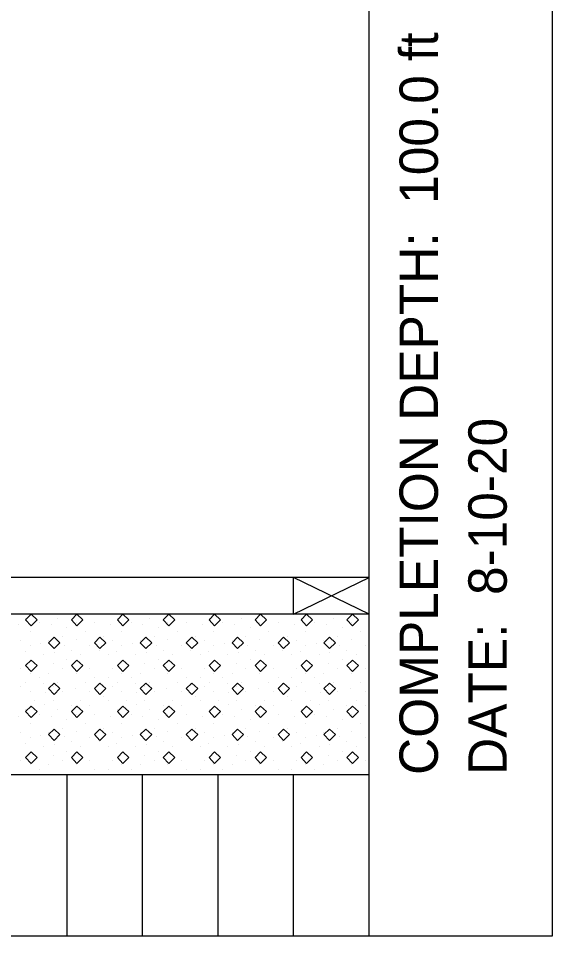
# Model space of a CAD drawing. Extents: x 1313964 to 1316843, y 2087046 to 2096619.
# Drawn here: x 1314029.73 to 1314036.8, y 2089873.43 to 2089885.58 of the extents above; entities that cross this region are included whole.
import ezdxf

# ---------------------------------------------------------------- set-up
doc = ezdxf.new("R2010")
doc.units = 0
doc.layers.add('B-Sub-Contour', color=7, linetype='Continuous')
doc.layers.add('Default', color=7, linetype='Continuous')

# ---------------------------------------------------------------- blocks, each defined once
blk = doc.blocks.new('POINT_DISPLAY')
at = {"layer": 'Default'}
blk.add_line((0, 0), (0, 0), dxfattribs=at)

msp = doc.modelspace()

# ---------------------------------------------------------------- linework, layer by layer
at = {"layer": 'B-Sub-Contour'}
for points in [[(1314036.804, 2089873.434), (1314036.804, 2089916.306), (1313975.385, 2089916.306), (1313975.385, 2089873.434), (1314036.804, 2089873.434)], [(1314034.372, 2089873.434), (1314034.372, 2089916.306)], [(1314034.372, 2089878.178), (1313989.372, 2089878.178)], [(1314033.372, 2089877.691), (1314034.372, 2089878.178)], [(1314034.372, 2089877.691), (1314033.372, 2089878.178)], [(1314033.372, 2089877.691), (1314033.372, 2089878.178)], [(1314034.372, 2089877.691), (1314034.372, 2089878.178)], [(1314034.372, 2089877.691), (1313982.683, 2089877.691)], [(1314034.372, 2089875.563), (1313982.683, 2089875.563)], [(1314030.372, 2089873.434), (1314030.372, 2089875.563)], [(1314030.372, 2089873.434), (1314030.372, 2089875.563)], [(1314031.372, 2089873.434), (1314031.372, 2089875.563)], [(1314032.372, 2089873.434), (1314032.372, 2089875.563)], [(1314032.372, 2089873.434), (1314032.372, 2089875.563)], [(1314033.372, 2089873.434), (1314033.372, 2089875.563)], [(1314034.372, 2089875.319), (1314034.372, 2089875.563)], [(1314034.372, 2089875.319), (1314034.372, 2089875.563)], [(1314034.372, 2089873.434), (1314034.372, 2089873.678)], [(1314034.372, 2089873.434), (1314034.372, 2089873.678)]]:
    msp.add_lwpolyline(points, dxfattribs=at)
for points in [[(1314029.894, 2089877.691), (1314029.821, 2089877.618), (1314029.894, 2089877.539), (1314029.973, 2089877.618)], [(1314030.502, 2089877.691), (1314030.429, 2089877.618), (1314030.502, 2089877.539), (1314030.581, 2089877.618)], [(1314031.11, 2089877.691), (1314031.037, 2089877.618), (1314031.11, 2089877.539), (1314031.189, 2089877.618)], [(1314031.718, 2089877.691), (1314031.645, 2089877.618), (1314031.718, 2089877.539), (1314031.797, 2089877.618)], [(1314032.326, 2089877.691), (1314032.253, 2089877.618), (1314032.326, 2089877.539), (1314032.405, 2089877.618)], [(1314032.934, 2089877.691), (1314032.861, 2089877.618), (1314032.934, 2089877.539), (1314033.014, 2089877.618)], [(1314033.543, 2089877.691), (1314033.47, 2089877.618), (1314033.543, 2089877.539), (1314033.622, 2089877.618)], [(1314034.151, 2089877.691), (1314034.078, 2089877.618), (1314034.151, 2089877.539), (1314034.23, 2089877.618)], [(1314030.198, 2089877.387), (1314030.125, 2089877.314), (1314030.198, 2089877.235), (1314030.277, 2089877.314)], [(1314030.806, 2089877.387), (1314030.733, 2089877.314), (1314030.806, 2089877.235), (1314030.885, 2089877.314)], [(1314031.414, 2089877.387), (1314031.341, 2089877.314), (1314031.414, 2089877.235), (1314031.493, 2089877.314)], [(1314032.022, 2089877.387), (1314031.949, 2089877.314), (1314032.022, 2089877.235), (1314032.101, 2089877.314)], [(1314032.63, 2089877.387), (1314032.557, 2089877.314), (1314032.63, 2089877.235), (1314032.709, 2089877.314)], [(1314033.239, 2089877.387), (1314033.166, 2089877.314), (1314033.239, 2089877.235), (1314033.318, 2089877.314)], [(1314033.847, 2089877.387), (1314033.774, 2089877.314), (1314033.847, 2089877.235), (1314033.926, 2089877.314)], [(1314029.894, 2089877.083), (1314029.821, 2089877.01), (1314029.894, 2089876.931), (1314029.973, 2089877.01)], [(1314030.502, 2089877.083), (1314030.429, 2089877.01), (1314030.502, 2089876.931), (1314030.581, 2089877.01)], [(1314031.11, 2089877.083), (1314031.037, 2089877.01), (1314031.11, 2089876.931), (1314031.189, 2089877.01)], [(1314031.718, 2089877.083), (1314031.645, 2089877.01), (1314031.718, 2089876.931), (1314031.797, 2089877.01)], [(1314032.326, 2089877.083), (1314032.253, 2089877.01), (1314032.326, 2089876.931), (1314032.405, 2089877.01)], [(1314032.934, 2089877.083), (1314032.861, 2089877.01), (1314032.934, 2089876.931), (1314033.014, 2089877.01)], [(1314033.543, 2089877.083), (1314033.47, 2089877.01), (1314033.543, 2089876.931), (1314033.622, 2089877.01)], [(1314034.151, 2089877.083), (1314034.078, 2089877.01), (1314034.151, 2089876.931), (1314034.23, 2089877.01)], [(1314030.198, 2089876.779), (1314030.125, 2089876.706), (1314030.198, 2089876.627), (1314030.277, 2089876.706)], [(1314030.806, 2089876.779), (1314030.733, 2089876.706), (1314030.806, 2089876.627), (1314030.885, 2089876.706)], [(1314031.414, 2089876.779), (1314031.341, 2089876.706), (1314031.414, 2089876.627), (1314031.493, 2089876.706)], [(1314032.022, 2089876.779), (1314031.949, 2089876.706), (1314032.022, 2089876.627), (1314032.101, 2089876.706)], [(1314032.63, 2089876.779), (1314032.557, 2089876.706), (1314032.63, 2089876.627), (1314032.709, 2089876.706)], [(1314033.239, 2089876.779), (1314033.166, 2089876.706), (1314033.239, 2089876.627), (1314033.318, 2089876.706)], [(1314033.847, 2089876.779), (1314033.774, 2089876.706), (1314033.847, 2089876.627), (1314033.926, 2089876.706)], [(1314029.894, 2089876.475), (1314029.821, 2089876.402), (1314029.894, 2089876.323), (1314029.973, 2089876.402)], [(1314030.502, 2089876.475), (1314030.429, 2089876.402), (1314030.502, 2089876.323), (1314030.581, 2089876.402)], [(1314031.11, 2089876.475), (1314031.037, 2089876.402), (1314031.11, 2089876.323), (1314031.189, 2089876.402)], [(1314031.718, 2089876.475), (1314031.645, 2089876.402), (1314031.718, 2089876.323), (1314031.797, 2089876.402)], [(1314032.326, 2089876.475), (1314032.253, 2089876.402), (1314032.326, 2089876.323), (1314032.405, 2089876.402)], [(1314032.934, 2089876.475), (1314032.861, 2089876.402), (1314032.934, 2089876.323), (1314033.014, 2089876.402)], [(1314033.543, 2089876.475), (1314033.47, 2089876.402), (1314033.543, 2089876.323), (1314033.622, 2089876.402)], [(1314034.151, 2089876.475), (1314034.078, 2089876.402), (1314034.151, 2089876.323), (1314034.23, 2089876.402)], [(1314030.198, 2089876.171), (1314030.125, 2089876.098), (1314030.198, 2089876.019), (1314030.277, 2089876.098)], [(1314030.806, 2089876.171), (1314030.733, 2089876.098), (1314030.806, 2089876.019), (1314030.885, 2089876.098)], [(1314031.414, 2089876.171), (1314031.341, 2089876.098), (1314031.414, 2089876.019), (1314031.493, 2089876.098)], [(1314032.022, 2089876.171), (1314031.949, 2089876.098), (1314032.022, 2089876.019), (1314032.101, 2089876.098)], [(1314032.63, 2089876.171), (1314032.557, 2089876.098), (1314032.63, 2089876.019), (1314032.709, 2089876.098)], [(1314033.239, 2089876.171), (1314033.166, 2089876.098), (1314033.239, 2089876.019), (1314033.318, 2089876.098)], [(1314033.847, 2089876.171), (1314033.774, 2089876.098), (1314033.847, 2089876.019), (1314033.926, 2089876.098)], [(1314029.894, 2089875.867), (1314029.821, 2089875.794), (1314029.894, 2089875.715), (1314029.973, 2089875.794)], [(1314030.502, 2089875.867), (1314030.429, 2089875.794), (1314030.502, 2089875.715), (1314030.581, 2089875.794)], [(1314031.11, 2089875.867), (1314031.037, 2089875.794), (1314031.11, 2089875.715), (1314031.189, 2089875.794)], [(1314031.718, 2089875.867), (1314031.645, 2089875.794), (1314031.718, 2089875.715), (1314031.797, 2089875.794)], [(1314032.326, 2089875.867), (1314032.253, 2089875.794), (1314032.326, 2089875.715), (1314032.405, 2089875.794)], [(1314032.934, 2089875.867), (1314032.861, 2089875.794), (1314032.934, 2089875.715), (1314033.014, 2089875.794)], [(1314033.543, 2089875.867), (1314033.47, 2089875.794), (1314033.543, 2089875.715), (1314033.622, 2089875.794)], [(1314034.151, 2089875.867), (1314034.078, 2089875.794), (1314034.151, 2089875.715), (1314034.23, 2089875.794)]]:
    msp.add_lwpolyline(points, close=True, dxfattribs=at)

# ---------------------------------------------------------------- block references
at = {"layer": 'B-Sub-Contour', "xscale": 0.019951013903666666, "yscale": 0.019951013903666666, "rotation": 90}
for p in [(1314029.821, 2089877.641), (1314030.247, 2089877.641), (1314031.037, 2089877.641), (1314031.463, 2089877.641), (1314032.253, 2089877.641), (1314032.679, 2089877.641), (1314033.47, 2089877.641), (1314033.895, 2089877.641), (1314029.73, 2089877.555), (1314030.003, 2089877.58), (1314030.158, 2089877.552), (1314030.368, 2089877.519), (1314030.49, 2089877.58), (1314030.733, 2089877.58), (1314030.946, 2089877.555), (1314031.22, 2089877.58), (1314031.374, 2089877.552), (1314031.584, 2089877.519), (1314031.706, 2089877.58), (1314031.949, 2089877.58), (1314032.162, 2089877.555), (1314032.436, 2089877.58), (1314032.591, 2089877.552), (1314032.801, 2089877.519), (1314032.922, 2089877.58), (1314033.166, 2089877.58), (1314033.378, 2089877.555), (1314033.652, 2089877.58), (1314033.807, 2089877.552), (1314034.017, 2089877.519), (1314034.139, 2089877.58), (1314029.882, 2089877.458), (1314030.307, 2089877.398), (1314030.611, 2089877.458), (1314030.855, 2089877.398), (1314031.098, 2089877.458), (1314031.524, 2089877.398), (1314031.828, 2089877.458), (1314032.071, 2089877.398), (1314032.314, 2089877.458), (1314032.74, 2089877.398), (1314033.044, 2089877.458), (1314033.287, 2089877.398), (1314033.53, 2089877.458), (1314033.956, 2089877.398), (1314034.26, 2089877.458), (1314029.76, 2089877.337), (1314029.882, 2089877.276), (1314030.02, 2089877.307), (1314030.125, 2089877.337), (1314030.332, 2089877.282), (1314030.49, 2089877.359), (1314030.672, 2089877.276), (1314030.976, 2089877.337), (1314031.098, 2089877.276), (1314031.236, 2089877.307), (1314031.341, 2089877.337), (1314031.549, 2089877.282), (1314031.706, 2089877.359), (1314031.889, 2089877.276), (1314032.193, 2089877.337), (1314032.314, 2089877.276), (1314032.452, 2089877.307), (1314032.557, 2089877.337), (1314032.765, 2089877.282), (1314032.922, 2089877.359), (1314033.105, 2089877.276), (1314033.409, 2089877.337), (1314033.53, 2089877.276), (1314033.669, 2089877.307), (1314033.774, 2089877.337), (1314033.981, 2089877.282), (1314034.139, 2089877.359), (1314034.321, 2089877.276), (1314029.815, 2089877.196), (1314030.064, 2089877.154), (1314030.205, 2089877.188), (1314030.429, 2089877.215), (1314030.551, 2089877.154), (1314030.794, 2089877.215), (1314030.916, 2089877.154), (1314031.032, 2089877.196), (1314031.28, 2089877.154), (1314031.421, 2089877.188), (1314031.645, 2089877.215), (1314031.767, 2089877.154), (1314032.01, 2089877.215), (1314032.132, 2089877.154), (1314032.248, 2089877.196), (1314032.497, 2089877.154), (1314032.638, 2089877.188), (1314032.861, 2089877.215), (1314032.983, 2089877.154), (1314033.226, 2089877.215), (1314033.348, 2089877.154), (1314033.464, 2089877.196), (1314033.713, 2089877.154), (1314033.854, 2089877.188), (1314034.078, 2089877.215), (1314034.199, 2089877.154), (1314029.943, 2089877.033), (1314030.186, 2089877.033), (1314030.368, 2089877.094), (1314031.159, 2089877.033), (1314031.402, 2089877.033), (1314031.584, 2089877.094), (1314032.375, 2089877.033), (1314032.618, 2089877.033), (1314032.801, 2089877.094), (1314033.591, 2089877.033), (1314033.834, 2089877.033), (1314034.017, 2089877.094), (1314029.76, 2089876.972), (1314029.882, 2089876.911), (1314030.125, 2089876.911), (1314030.307, 2089876.972), (1314030.49, 2089876.911), (1314030.672, 2089876.972), (1314030.976, 2089876.972), (1314031.098, 2089876.911), (1314031.341, 2089876.911), (1314031.524, 2089876.972), (1314031.706, 2089876.911), (1314031.889, 2089876.972), (1314032.193, 2089876.972), (1314032.314, 2089876.911), (1314032.557, 2089876.911), (1314032.74, 2089876.972), (1314032.922, 2089876.911), (1314033.105, 2089876.972), (1314033.409, 2089876.972), (1314033.53, 2089876.911), (1314033.774, 2089876.911), (1314033.956, 2089876.972), (1314034.139, 2089876.911), (1314034.321, 2089876.972), (1314029.821, 2089876.79), (1314030.003, 2089876.85), (1314030.247, 2089876.79), (1314030.611, 2089876.79), (1314030.733, 2089876.85), (1314030.794, 2089876.776), (1314030.916, 2089876.85), (1314031.037, 2089876.79), (1314031.22, 2089876.85), (1314031.463, 2089876.79), (1314031.828, 2089876.79), (1314031.949, 2089876.85), (1314032.01, 2089876.776), (1314032.132, 2089876.85), (1314032.253, 2089876.79), (1314032.436, 2089876.85), (1314032.679, 2089876.79), (1314033.044, 2089876.79), (1314033.166, 2089876.85), (1314033.226, 2089876.776), (1314033.348, 2089876.85), (1314033.47, 2089876.79), (1314033.652, 2089876.85), (1314033.895, 2089876.79), (1314034.26, 2089876.79), (1314029.76, 2089876.729), (1314029.882, 2089876.668), (1314030.064, 2089876.768), (1314030.186, 2089876.729), (1314030.307, 2089876.668), (1314030.476, 2089876.712), (1314030.672, 2089876.668), (1314030.976, 2089876.729), (1314031.098, 2089876.668), (1314031.28, 2089876.768), (1314031.402, 2089876.729), (1314031.524, 2089876.668), (1314031.692, 2089876.712), (1314031.889, 2089876.668), (1314032.193, 2089876.729), (1314032.314, 2089876.668), (1314032.497, 2089876.768), (1314032.618, 2089876.729), (1314032.74, 2089876.668), (1314032.908, 2089876.712), (1314033.105, 2089876.668), (1314033.409, 2089876.729), (1314033.53, 2089876.668), (1314033.713, 2089876.768), (1314033.834, 2089876.729), (1314033.956, 2089876.668), (1314034.125, 2089876.712), (1314034.321, 2089876.668), (1314029.943, 2089876.546), (1314030.081, 2089876.648), (1314030.186, 2089876.546), (1314030.551, 2089876.546), (1314030.855, 2089876.607), (1314030.916, 2089876.546), (1314031.159, 2089876.546), (1314031.297, 2089876.648), (1314031.402, 2089876.546), (1314031.767, 2089876.546), (1314032.071, 2089876.607), (1314032.132, 2089876.546), (1314032.375, 2089876.546), (1314032.513, 2089876.648), (1314032.618, 2089876.546), (1314032.983, 2089876.546), (1314033.287, 2089876.607), (1314033.348, 2089876.546), (1314033.591, 2089876.546), (1314033.729, 2089876.648), (1314033.834, 2089876.546), (1314034.199, 2089876.546), (1314029.821, 2089876.425), (1314030.072, 2089876.502), (1314030.247, 2089876.425), (1314030.429, 2089876.485), (1314030.672, 2089876.488), (1314031.037, 2089876.425), (1314031.289, 2089876.502), (1314031.463, 2089876.425), (1314031.645, 2089876.485), (1314031.889, 2089876.488), (1314032.253, 2089876.425), (1314032.505, 2089876.502), (1314032.679, 2089876.425), (1314032.861, 2089876.485), (1314033.105, 2089876.488), (1314033.47, 2089876.425), (1314033.721, 2089876.502), (1314033.895, 2089876.425), (1314034.078, 2089876.485), (1314034.321, 2089876.488), (1314029.73, 2089876.339), (1314030.003, 2089876.364), (1314030.158, 2089876.336), (1314030.368, 2089876.303), (1314030.49, 2089876.364), (1314030.733, 2089876.364), (1314030.946, 2089876.339), (1314031.22, 2089876.364), (1314031.374, 2089876.336), (1314031.584, 2089876.303), (1314031.706, 2089876.364), (1314031.949, 2089876.364), (1314032.162, 2089876.339), (1314032.436, 2089876.364), (1314032.591, 2089876.336), (1314032.801, 2089876.303), (1314032.922, 2089876.364), (1314033.166, 2089876.364), (1314033.378, 2089876.339), (1314033.652, 2089876.364), (1314033.807, 2089876.336), (1314034.017, 2089876.303), (1314034.139, 2089876.364), (1314029.882, 2089876.242), (1314030.307, 2089876.181), (1314030.611, 2089876.242), (1314030.855, 2089876.181), (1314031.098, 2089876.242), (1314031.524, 2089876.181), (1314031.828, 2089876.242), (1314032.071, 2089876.181), (1314032.314, 2089876.242), (1314032.74, 2089876.181), (1314033.044, 2089876.242), (1314033.287, 2089876.181), (1314033.53, 2089876.242), (1314033.956, 2089876.181), (1314034.26, 2089876.242), (1314029.76, 2089876.121), (1314029.882, 2089876.06), (1314030.02, 2089876.09), (1314030.125, 2089876.121), (1314030.332, 2089876.066), (1314030.49, 2089876.143), (1314030.672, 2089876.06), (1314030.976, 2089876.121), (1314031.098, 2089876.06), (1314031.236, 2089876.09), (1314031.341, 2089876.121), (1314031.549, 2089876.066), (1314031.706, 2089876.143), (1314031.889, 2089876.06), (1314032.193, 2089876.121), (1314032.314, 2089876.06), (1314032.452, 2089876.09), (1314032.557, 2089876.121), (1314032.765, 2089876.066), (1314032.922, 2089876.143), (1314033.105, 2089876.06), (1314033.409, 2089876.121), (1314033.53, 2089876.06), (1314033.669, 2089876.09), (1314033.774, 2089876.121), (1314033.981, 2089876.066), (1314034.139, 2089876.143), (1314034.321, 2089876.06), (1314029.815, 2089875.98), (1314030.064, 2089875.938), (1314030.205, 2089875.972), (1314030.429, 2089875.999), (1314030.551, 2089875.938), (1314030.794, 2089875.999), (1314030.916, 2089875.938), (1314031.032, 2089875.98), (1314031.28, 2089875.938), (1314031.421, 2089875.972), (1314031.645, 2089875.999), (1314031.767, 2089875.938), (1314032.01, 2089875.999), (1314032.132, 2089875.938), (1314032.248, 2089875.98), (1314032.497, 2089875.938), (1314032.638, 2089875.972), (1314032.861, 2089875.999), (1314032.983, 2089875.938), (1314033.226, 2089875.999), (1314033.348, 2089875.938), (1314033.464, 2089875.98), (1314033.713, 2089875.938), (1314033.854, 2089875.972), (1314034.078, 2089875.999), (1314034.199, 2089875.938), (1314029.943, 2089875.817), (1314030.186, 2089875.817), (1314030.368, 2089875.877), (1314031.159, 2089875.817), (1314031.402, 2089875.817), (1314031.584, 2089875.877), (1314032.375, 2089875.817), (1314032.618, 2089875.817), (1314032.801, 2089875.877), (1314033.591, 2089875.817), (1314033.834, 2089875.817), (1314034.017, 2089875.877), (1314029.76, 2089875.756), (1314029.882, 2089875.695), (1314030.125, 2089875.695), (1314030.307, 2089875.756), (1314030.49, 2089875.695), (1314030.672, 2089875.756), (1314030.976, 2089875.756), (1314031.098, 2089875.695), (1314031.341, 2089875.695), (1314031.524, 2089875.756), (1314031.706, 2089875.695), (1314031.889, 2089875.756), (1314032.193, 2089875.756), (1314032.314, 2089875.695), (1314032.557, 2089875.695), (1314032.74, 2089875.756), (1314032.922, 2089875.695), (1314033.105, 2089875.756), (1314033.409, 2089875.756), (1314033.53, 2089875.695), (1314033.774, 2089875.695), (1314033.956, 2089875.756), (1314034.139, 2089875.695), (1314034.321, 2089875.756), (1314029.821, 2089875.573), (1314030.003, 2089875.634), (1314030.247, 2089875.573), (1314030.611, 2089875.573), (1314030.733, 2089875.634), (1314030.916, 2089875.634), (1314031.037, 2089875.573), (1314031.22, 2089875.634), (1314031.463, 2089875.573), (1314031.828, 2089875.573), (1314031.949, 2089875.634), (1314032.132, 2089875.634), (1314032.253, 2089875.573), (1314032.436, 2089875.634), (1314032.679, 2089875.573), (1314033.044, 2089875.573), (1314033.166, 2089875.634), (1314033.348, 2089875.634), (1314033.47, 2089875.573), (1314033.652, 2089875.634), (1314033.895, 2089875.573), (1314034.26, 2089875.573)]:
    msp.add_blockref('POINT_DISPLAY', p, dxfattribs=at)

# ---------------------------------------------------------------- texts
at = {"layer": 'B-Sub-Contour'}
for s, p in [('COMPLETION DEPTH:  100.0 ft', (1314035.284, 2089875.563)), ('DATE:  8-10-20', (1314036.196, 2089875.563))]:
    msp.add_text(s, height=0.50899, rotation=90, dxfattribs=at).set_placement(p)

doc.saveas('drawing.dxf')
